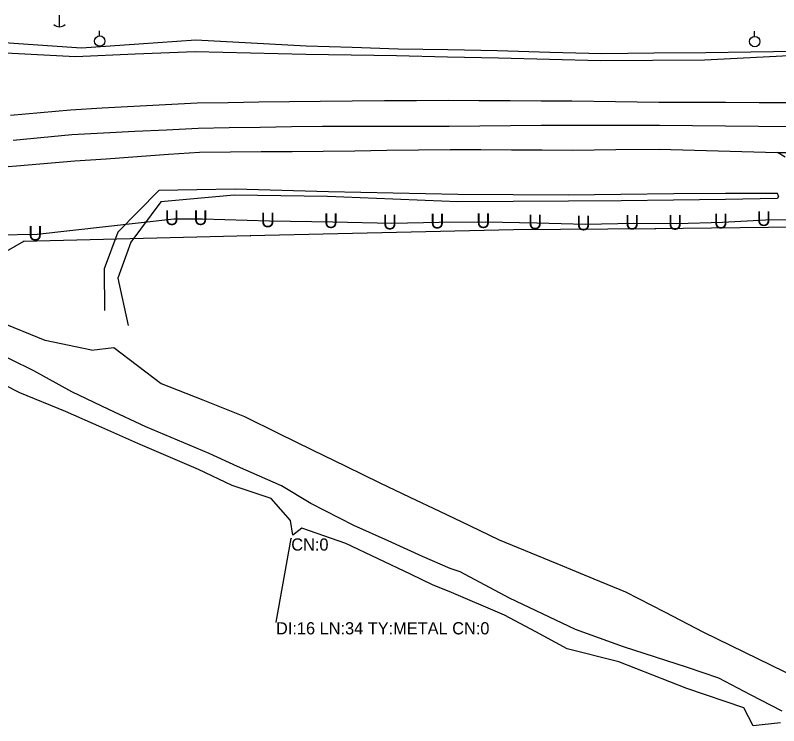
# Model space of a CAD drawing. Extents: x 1939239 to 1943096, y 531224 to 537447.
# Drawn here: x 1941037.4 to 1941349.8, y 534557.9 to 534848.8 of the extents above; entities that cross this region are included whole.
import ezdxf

# ---------------------------------------------------------------- set-up
doc = ezdxf.new("R2010")
doc.units = 0
for name, color, linetype in [('Default', 7, 'Continuous'), ('S_CROSS_DRAIN', 7, 'Continuous'), ('S_CROSS_DRAIN_ANNOT', 7, 'Continuous'), ('S_DITCHLINE', 7, 'Continuous'), ('S_DRG_PT_SYM', 7, 'Continuous'), ('S_EDGE_BITUMINOUS', 7, 'Continuous'), ('S_EDGE_PAVEMENT', 7, 'Continuous'), ('S_PAVEMENT_CROWN', 7, 'Continuous'), ('S_UNDERGROUND_CABLE', 7, 'Continuous'), ('S_UTILITY_POLE', 7, 'Continuous'), ('S_UTL_PT_SYM', 7, 'Continuous'), ('S_WATER_UTILITIES', 7, 'Continuous')]:
    doc.layers.add(name, color=color, linetype=linetype)

msp = doc.modelspace()

# ---------------------------------------------------------------- linework, layer by layer
at = {"layer": 'S_CROSS_DRAIN'}
msp.add_line((1941144.06, 534600.31), (1941150.3, 534634.61), dxfattribs=at)
at = {"layer": 'S_DITCHLINE'}
for points in [[(1941356.72, 534832.94), (1941356.86, 534833.91), (1941338.36, 534833.68), (1941319.86, 534833.44), (1941298.62, 534833.2), (1941277.38, 534832.97), (1941256.04, 534833.57), (1941234.71, 534834.18), (1941214.38, 534834.56), (1941194.04, 534834.93), (1941175.23, 534835.53), (1941156.41, 534836.12), (1941133.85, 534837.32), (1941111.3, 534838.52), (1941087.89, 534836.93), (1941064.48, 534835.33), (1941042.69, 534836.83), (1941020.9, 534838.32), (1940996.16, 534839.27), (1940971.42, 534840.22), (1940957.88, 534838.44), (1940944.34, 534836.67), (1940930.79, 534834.89), (1940917.25, 534833.11)], [(1941356.66, 534832.31), (1941338.01, 534831.38), (1941319.37, 534830.45), (1941298.07, 534830.31), (1941276.77, 534830.18), (1941255.95, 534830.68), (1941235.14, 534831.17), (1941214.28, 534831.69), (1941193.41, 534832.21), (1941174.87, 534832.43), (1941156.32, 534832.65), (1941133.65, 534833.25), (1941110.99, 534833.85), (1941086.48, 534832.82), (1941061.97, 534831.78), (1941041.25, 534832.89), (1941020.53, 534834.01), (1940995.73, 534834.15), (1940970.92, 534834.29), (1940957.78, 534832.82), (1940944.63, 534831.35), (1940931.48, 534829.87), (1940918.33, 534828.4)], [(1941349.24, 534775.84), (1941328.01, 534775.75), (1941306.77, 534775.67), (1941285.21, 534775.38), (1941263.65, 534775.1), (1941241.06, 534775.27), (1941218.47, 534775.45), (1941205.24, 534775.72), (1941192.01, 534776), (1941178.78, 534776.28), (1941165.55, 534776.55), (1941146.46, 534777.06), (1941127.37, 534777.57), (1941111.72, 534777.32), (1941096.08, 534777.06), (1941079.27, 534760.01), (1941073.76, 534744.98)], [(1941349.59, 534774.66), (1941349.26, 534773.73), (1941328, 534773.41), (1941306.73, 534773.09), (1941285.24, 534772.85), (1941263.75, 534772.61), (1941241.11, 534772.52), (1941218.47, 534772.44), (1941205.15, 534772.96), (1941191.83, 534773.49), (1941178.5, 534774.01), (1941165.18, 534774.53), (1941146.08, 534774.86), (1941126.98, 534775.19), (1941111.94, 534773.81), (1941096.9, 534772.44), (1941084.59, 534755.9), (1941079.32, 534741.11)], [(1941349.59, 534774.66), (1941349.24, 534775.84)], [(1941073.76, 534744.98), (1941073.92, 534727.9)], [(1941079.32, 534741.11), (1941083.61, 534721.7)], [(1941049.66, 534715.63), (1941030.84, 534723.24)], [(1941068.49, 534711.65), (1941049.66, 534715.63)], [(1941351.14, 534563.83), (1941338.22, 534570.58), (1941325.29, 534577.34), (1941312.42, 534581.8), (1941299.35, 534586.02), (1941286.29, 534590.25), (1941266.55, 534597.31), (1941253.07, 534603.75), (1941239.58, 534610.18), (1941219.36, 534620.88), (1941215.31, 534622.26), (1941204, 534627.24), (1941189.97, 534633.56), (1941175.94, 534639.88), (1941158.25, 534648.94), (1941146.26, 534656.13), (1941128.32, 534663.99), (1941116.67, 534669.39), (1941103.72, 534674.83), (1941090.77, 534680.26), (1941075.61, 534687.41), (1941060.45, 534694.56), (1941045.02, 534703.25), (1941026, 534712.47)], [(1941068.49, 534711.65), (1941077.68, 534712.82), (1941097.05, 534698.05), (1941114.08, 534691.29), (1941131.11, 534684.53), (1941144.96, 534677.73), (1941158.82, 534670.93), (1941172.68, 534664.13), (1941186.53, 534657.33), (1941198.76, 534651.51), (1941210.98, 534645.69), (1941223.21, 534639.87), (1941235.43, 534634.05), (1941248.32, 534628.74), (1941261.21, 534623.42), (1941274.1, 534618.11), (1941286.99, 534612.79), (1941302.96, 534604.48), (1941318.92, 534596.18), (1941341.03, 534585.44), (1941363.13, 534574.69)], [(1941350.41, 534559.11), (1941339.34, 534557.91), (1941335.46, 534565.24), (1941312.11, 534573.12), (1941298.23, 534578.62), (1941284.34, 534584.12), (1941263.13, 534589.38), (1941250.35, 534596.31), (1941237.57, 534603.24), (1941214.84, 534612.86), (1941208.37, 534615.48), (1941199.04, 534620.03), (1941185.83, 534626.25), (1941172.62, 534632.47), (1941154.57, 534638.85), (1941150.87, 534635.97), (1941150.01, 534641.99), (1941142.12, 534651), (1941126.1, 534656.3), (1941112.39, 534662.84), (1941099.97, 534668.13), (1941087.55, 534673.43), (1941072.72, 534679.99), (1941057.89, 534686.55), (1941039.25, 534694.23), (1941021.19, 534703.39)]]:
    msp.add_lwpolyline(points, dxfattribs=at)
at = {"layer": 'S_DRG_PT_SYM'}
for points in [[(1941150.3, 534634.61), (1941150.3, 534634.66), (1941150.3, 534634.61), (1941150.25, 534634.61), (1941150.3, 534634.61), (1941150.3, 534634.56), (1941150.3, 534634.61), (1941150.35, 534634.61)], [(1941144.06, 534600.31), (1941144.06, 534600.36), (1941144.06, 534600.31), (1941144.01, 534600.31), (1941144.06, 534600.31), (1941144.06, 534600.26), (1941144.06, 534600.31), (1941144.11, 534600.31)]]:
    msp.add_lwpolyline(points, dxfattribs=at)
at = {"layer": 'S_EDGE_BITUMINOUS'}
msp.add_lwpolyline([(1941352.32, 534790.7), (1941349.24, 534792.57)], dxfattribs=at)
at = {"layer": 'S_EDGE_PAVEMENT'}
for points in [[(1941035.48, 534807.92), (1941059.93, 534810.12), (1941072.91, 534810.82), (1941085.89, 534811.52), (1941098.87, 534812.23), (1941111.85, 534812.93), (1941124.42, 534813.11), (1941137, 534813.29), (1941149.58, 534813.48), (1941162.16, 534813.66), (1941175.27, 534813.74), (1941188.38, 534813.82), (1941201.49, 534813.89), (1941214.6, 534813.97), (1941227.24, 534813.9), (1941239.87, 534813.84), (1941252.5, 534813.77), (1941265.14, 534813.71), (1941282.9, 534813.47), (1941300.67, 534813.23), (1941314.35, 534813.19), (1941328.04, 534813.14), (1941341.72, 534813.09), (1941355.4, 534813.04)], [(1941013.88, 534785.21), (1941037.83, 534787.17), (1941061.77, 534789.14), (1941074.51, 534790.05), (1941087.25, 534790.96), (1941100, 534791.87), (1941112.74, 534792.78), (1941125.39, 534792.86), (1941138.04, 534792.95), (1941150.7, 534793.04), (1941163.35, 534793.12), (1941176.35, 534793.31), (1941189.35, 534793.49), (1941202.34, 534793.68), (1941215.34, 534793.87), (1941227.87, 534793.8), (1941240.39, 534793.74), (1941252.91, 534793.68), (1941265.43, 534793.61), (1941283.1, 534793.77), (1941300.77, 534793.93), (1941325, 534793.25), (1941349.24, 534792.57), (1941372.33, 534792.63)]]:
    msp.add_lwpolyline(points, dxfattribs=at)
at = {"layer": 'S_PAVEMENT_CROWN'}
msp.add_lwpolyline([(1941036.52, 534797.59), (1941060.48, 534799.96), (1941073.4, 534800.62), (1941086.31, 534801.28), (1941099.23, 534801.94), (1941112.15, 534802.6), (1941124.89, 534802.8), (1941137.63, 534802.99), (1941150.37, 534803.18), (1941163.12, 534803.37), (1941176.05, 534803.37), (1941188.99, 534803.37), (1941201.93, 534803.37), (1941214.87, 534803.37), (1941227.43, 534803.49), (1941240, 534803.61), (1941252.56, 534803.73), (1941265.13, 534803.84), (1941283.04, 534803.8), (1941300.96, 534803.76), (1941314.48, 534803.63), (1941327.99, 534803.51), (1941341.51, 534803.38), (1941355.02, 534803.25)], dxfattribs=at)
at = {"layer": 'S_UNDERGROUND_CABLE'}
for p, q in [((1941046.29, 534759.1), (1941102.18, 534765.42)), ((1941102.18, 534765.42), (1941113.94, 534765.45)), ((1941113.94, 534765.45), (1941141.45, 534764.55)), ((1941344.38, 534765.05), (1941360.88, 534765.26)), ((1941141.45, 534764.55), (1941167.27, 534764.21)), ((1941167.27, 534764.21), (1941191.38, 534763.65)), ((1941191.38, 534763.65), (1941210.79, 534764.05)), ((1941210.79, 534764.05), (1941229.63, 534764.21)), ((1941229.63, 534764.21), (1941250.84, 534763.74)), ((1941250.84, 534763.74), (1941270.62, 534763.27)), ((1941270.62, 534763.27), (1941290.53, 534763.6)), ((1941290.53, 534763.6), (1941308.09, 534763.53)), ((1941308.09, 534763.53), (1941326.81, 534764.04)), ((1941326.81, 534764.04), (1941344.38, 534765.05)), ((1940977.05, 534758.32), (1941046.29, 534759.1))]:
    msp.add_line(p, q, dxfattribs=at)
at = {"layer": 'S_UTILITY_POLE'}
for p, q in [((1941055.38, 534848.78), (1941055.38, 534844.05)), ((1941071.78, 534840.36), (1941071.78, 534842.47)), ((1941339.83, 534840.12), (1941339.83, 534842.23))]:
    msp.add_line(p, q, dxfattribs=at)
for centre in [(1941071.91, 534838.22), (1941339.95, 534837.98)]:
    msp.add_circle(centre, 2.13, dxfattribs=at)
msp.add_arc((1941055.45, 534847.48), 3.41, 226.3972, 313.6028, dxfattribs=at)
at = {"layer": 'S_UTL_PT_SYM'}
for points in [[(1941241.22, 534760.93), (1941241.22, 534760.98), (1941241.22, 534760.93), (1941241.17, 534760.93), (1941241.22, 534760.93), (1941241.22, 534760.88), (1941241.22, 534760.93), (1941241.27, 534760.93)], [(1941299.09, 534761.32), (1941299.09, 534761.37), (1941299.09, 534761.32), (1941299.04, 534761.32), (1941299.09, 534761.32), (1941299.09, 534761.27), (1941299.09, 534761.32), (1941299.14, 534761.32)], [(1941040.71, 534756.11), (1941040.71, 534756.16), (1941040.71, 534756.11), (1941040.66, 534756.11), (1941040.71, 534756.11), (1941040.71, 534756.06), (1941040.71, 534756.11), (1941040.76, 534756.11)], [(1941133.5, 534758.47), (1941133.5, 534758.52), (1941133.5, 534758.47), (1941133.45, 534758.47), (1941133.5, 534758.47), (1941133.5, 534758.42), (1941133.5, 534758.47), (1941133.55, 534758.47)]]:
    msp.add_lwpolyline(points, dxfattribs=at)
at = {"layer": 'S_WATER_UTILITIES'}
for p, q in [((1941241.22, 534760.93), (1941133.5, 534758.47)), ((1941299.09, 534761.32), (1941241.22, 534760.93)), ((1941362.93, 534762.12), (1941299.09, 534761.32)), ((1941040.71, 534756.11), (1940957.11, 534708.35)), ((1941133.5, 534758.47), (1941040.71, 534756.11))]:
    msp.add_line(p, q, dxfattribs=at)

# ---------------------------------------------------------------- texts
at = {"layer": 'Default'}
for p in [(1941098.55, 534762.88), (1941110.31, 534762.9), (1941340.75, 534762.51), (1941137.82, 534762), (1941163.64, 534761.67), (1941187.75, 534761.1), (1941207.17, 534761.5), (1941226, 534761.67), (1941247.21, 534761.19), (1941266.99, 534760.72), (1941286.9, 534761.05), (1941304.46, 534760.98), (1941323.18, 534761.5), (1941042.66, 534756.56)]:
    msp.add_text('U', height=6, dxfattribs=at).set_placement(p)
at = {"layer": 'S_CROSS_DRAIN_ANNOT'}
for s, p in [('CN:0', (1941150.3, 534629.61)), ('DI:16 LN:34 TY:METAL CN:0', (1941144.06, 534595.31))]:
    msp.add_text(s, height=5, dxfattribs=at).set_placement(p)

doc.saveas('drawing.dxf')
